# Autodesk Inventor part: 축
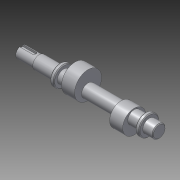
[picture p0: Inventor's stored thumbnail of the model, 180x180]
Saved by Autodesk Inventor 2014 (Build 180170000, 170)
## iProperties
Created: 2014-12
Part Number: 축
Material: 알루미늄 6061
Document SubType Name: Modeling
Designer: Owner
Mass: 170.354 g
Surface Area: 153.402 cm^2
Volume: 62.8614 cm^3
Density: 2.71 g/cm^3
Appearance: 알루미늄 - 평지
Author: Owner
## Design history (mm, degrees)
node "작업 평면1"
sketch "스케치1"
  geometry: L1 (-90, 0)-(90, 0); L2 (-90, 0)-(-90, 7.5); L3 (-90, 7.5)-(-66, 7.5); L4 (-66, 7.5)-(-66, 8.5); L5 (-66, 8.5)-(-39, 8.5); L6 (-39, 8.5)-(-39, 13); L7 (-39, 13)-(-34, 13); L8 (-34, 13)-(-34, 8.5); L9 (-34, 8.5)-(72, 8.5); L10 (72, 8.5)-(72, 13); L11 (72, 13)-(77, 13); L12 (77, 13)-(77, 8.5); L13 (77, 8.5)-(90, 8.5); L14 (90, 8.5)-(90, 0); 2 further points
  constraints: 28 end point, 11 parallel, 2 perpendicular, 1 coincident, 1 horizontal, 1 midpoint
  dimensions: "d1" = 180 distance of L1.start L1.end; "d2" = 15 diameter of L2.end L1; "d3" = 17 diameter of L5 L1; "d4" = 26 diameter of L7 L1; "d5" = 17 diameter of L13 L1; "d6" = 26 diameter of L11 L1; "d7" = 17 diameter of L9 L1; "d8" = 5 distance of L6.end L7.end; "d9" = 5 distance of L10.end L11.end; "d10" = 24 distance of L2.end L3.end; "d11" = 27 distance of L4.end L5.end; "d12" = 106 distance of L8.end L9.end
revolve "회전1" sketch "스케치1" stored, may be unused: angle "d13" = 90 deg
node "작업 평면2"
sketch "스케치4"
  geometry: C1 r 17.5 at (0, 6); 1 further point
  constraints: 1 centre point, 1 vertical alignment
  dimensions: "d17" = 35 diameter of C1; "d18" = 6 distance of C1.centre point (0, 0)
extrude "돌출1" join sketch "스케치4" distance "d19" = 17; taper "d20" = 0 deg
node "작업 평면3"
sketch "스케치5"
  geometry: C1 r 15 at (0, -5); 1 further point
  constraints: 1 centre point, 1 vertical alignment
  dimensions: "d22" = 30 diameter of C1; "d23" = 5 distance of C1.centre point (0, 0)
extrude "돌출2" join sketch "스케치5" distance "d24" = 17; taper "d25" = 0 deg
node "작업 평면4"
sketch "스케치6"
  geometry: L1 (7.5, -12)-(-7.5, -12) reference; L2 (-2.5, 5.5)-(-2.5, -12); L3 (2.5, 5.5)-(2.5, -12); A1 r 2.5 centre (0, 5.5) between (2.5, 5.5) and (-2.5, 5.5); 1 further point
  constraints: 4 end point, 2 perpendicular, 2 point on circle, 2 point on line, 2 tangent, 1 centre point, 1 vertical alignment
  dimensions: "d30" = 5 diameter of A1; "d31" = 20 dimension on A1 L1
extrude "돌출3" cut sketch "스케치6" distance "d32" = 3; taper "d33" = 0 deg
chamfer "모따기1" distance "d34" = 1; stored, may be unused: second distance "d35" = 2, angle "d36" = 45 deg
sketch "스케치8"
  geometry: 1 further point
node "솔리드1"
other parameters: "d0" = 0, "d14" = 14.5, "d21" = 14.5
